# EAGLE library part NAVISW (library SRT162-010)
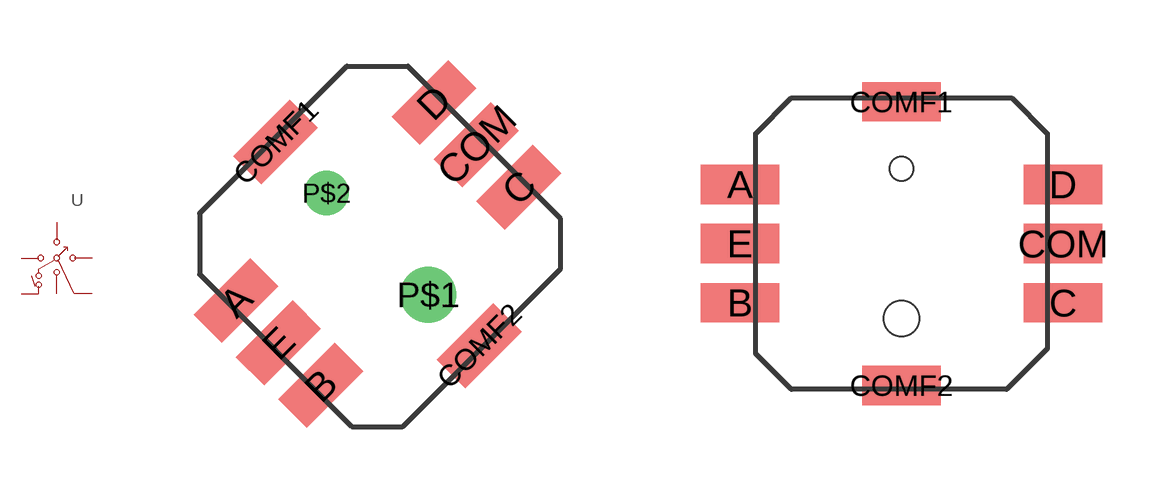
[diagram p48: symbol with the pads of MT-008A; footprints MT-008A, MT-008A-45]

Designator prefix -

## NAVISWMT-008A  [MT-008A]
A  A  pas
B  B  pas
C  C  pas
COM  COM  pas
D  D  pas
E  SEL  pas

## NAVISWMT-008A/45  [MT-008A-45]
Pads as for MT-008A

## Footprint MT-008A (pad centres in mm)
smd 2 x 1 rotated 45: A -3.536,-1.414; B -1.414,-3.536; C 3.536,1.414; COM 2.475,2.475; COMF1 -2.546,2.546; COMF2 2.546,-2.546; D 1.414,3.536; E -2.475,-2.475
drill 0.9 pad 1.3 round: P$1 1.27,-1.27
drill 0.6 pad 0.9 round: P$2 -1.27,1.27

## Footprint MT-008A-45 (pad centres in mm)
smd 2 x 1: A -4.1,1.5; B -4.1,-1.5; C 4.1,-1.5; COM 4.1,0; COMF1 0,3.6; COMF2 0,-3.6; D 4.1,1.5; E -4.1,0
hole 0.6 at 0,1.9
hole 0.9 at 0,-1.9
